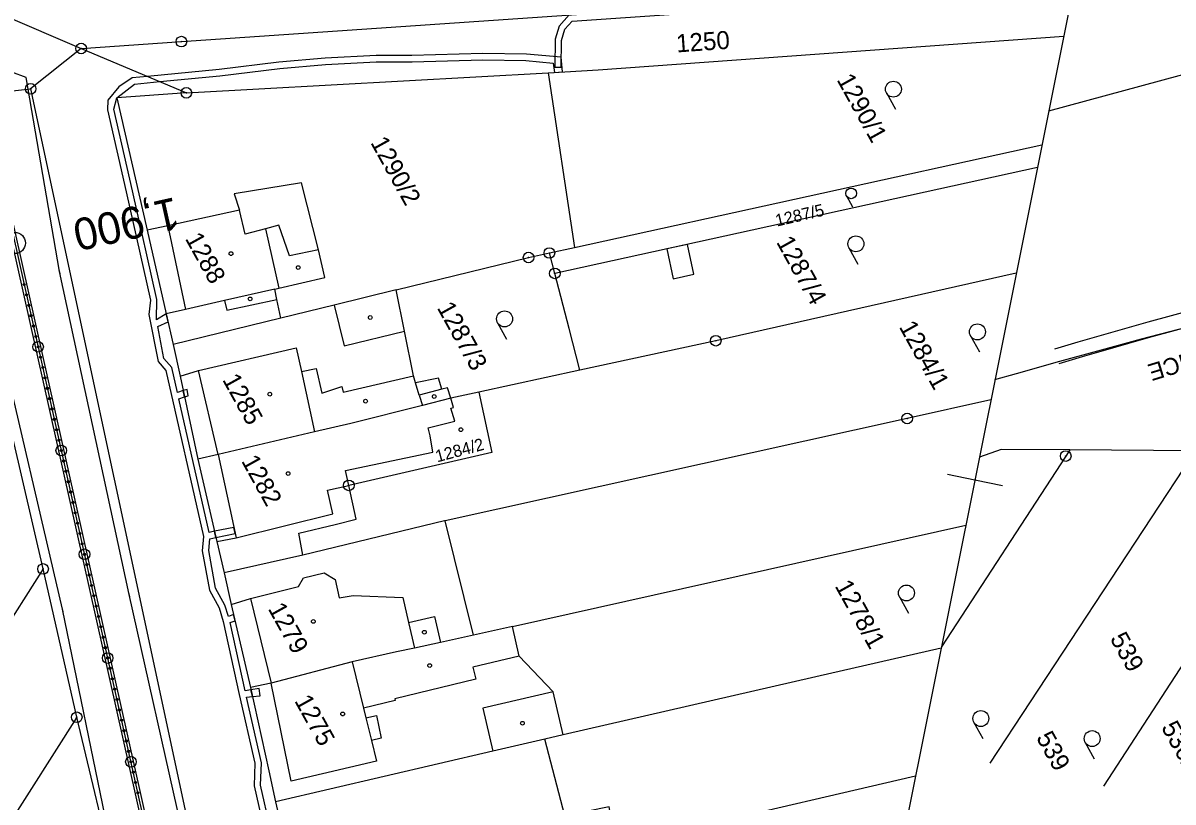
# Model space of a CAD drawing. Extents: x -548552 to -543113, y -1131925 to -1123599.
# Drawn here: x -548017.8 to -547909.6, y -1129833.4 to -1129760.1 of the extents above; entities that cross this region are included whole.
import ezdxf

# ---------------------------------------------------------------- set-up
doc = ezdxf.new("R2010")
doc.units = 0
for name, color, linetype in [('Hranice parcel', 7, 'Continuous'), ('NADZEMNÍ VEDENÍ VN', 7, 'Continuous'), ('Parcelní čísla', 7, 'Continuous'), ('Poz předměty', 7, 'Continuous'), ('Profile', 7, 'Continuous'), ('STANIČENÍ', 7, 'Continuous'), ('Vnitřní kresba', 7, 'Continuous'), ('Věcná břemena k části', 7, 'Continuous'), ('Značky bodu BP', 7, 'Continuous'), ('Značky budov', 7, 'Continuous'), ('Značky kultur', 7, 'Continuous'), ('ŽELEZNICE', 7, 'Continuous')]:
    doc.layers.add(name, color=color, linetype=linetype)

msp = doc.modelspace()

# ---------------------------------------------------------------- linework, layer by layer
at = {"layer": 'Hranice parcel'}
for p, q in [((-547921.25, -1129768.38), (-547893.05, -1129760.73)), ((-547921.25, -1129768.38), (-547893.05, -1129760.73)), ((-548012.34, -1129762.51), (-548017.09, -1129766.31)), ((-548012.34, -1129762.51), (-548002.43, -1129766.69)), ((-548002.43, -1129766.69), (-547968.36, -1129764.79)), ((-547968.36, -1129764.79), (-547965.9, -1129781.23)), ((-548026.4, -1129767.33), (-548017.09, -1129766.31)), ((-548026.4, -1129767.33), (-548017.09, -1129766.31)), ((-547965.9, -1129781.23), (-547921.89, -1129771.58)), ((-547922.32, -1129773.72), (-547967.75, -1129783.67)), ((-547968.26, -1129781.75), (-547965.9, -1129781.23)), ((-547967.75, -1129783.67), (-547968.26, -1129781.75)), ((-547993.53, -1129787.89), (-548003.66, -1129790.37)), ((-547965.41, -1129792.78), (-547974.91, -1129794.84)), ((-547974.91, -1129794.84), (-547977.55, -1129795.41)), ((-548015.92, -1129811.47), (-548018.75, -1129799.26)), ((-547907.46, -1129800.35), (-547919.28, -1129800.26)), ((-547975.4, -1129817.69), (-547978.07, -1129806.94)), ((-547991.48, -1129810.18), (-547998.89, -1129811.84)), ((-548015.92, -1129811.47), (-548041.34, -1129851.35)), ((-548012.75, -1129825.42), (-548015.92, -1129811.47)), ((-547971.74, -1129816.87), (-547975.4, -1129817.69)), ((-548012.75, -1129825.42), (-548032.91, -1129857.07)), ((-547966.95, -1129827.08), (-547968.68, -1129827.48)), ((-547961.98, -1129837.46), (-547933.79, -1129830.92)), ((-547994.03, -1129833.37), (-547991.57, -1129844.06))]:
    msp.add_line(p, q, dxfattribs=at)
for points in [[(-548019.13, -1129730.43), (-548027.65, -1129755.94), (-548012.34, -1129762.51)], [(-548012.34, -1129762.51), (-548002.9, -1129761.87), (-547963.89, -1129759.18), (-547918.79, -1129756.09)], [(-547968.36, -1129764.79), (-547963.68, -1129764.53), (-547919.84, -1129761.35)], [(-548017.09, -1129766.31), (-548001.35, -1129839.73), (-547987.65, -1129898.29)], [(-548017.09, -1129766.31), (-548001.35, -1129839.73), (-547987.65, -1129898.29)], [(-548002.43, -1129766.69), (-548008.99, -1129767.14), (-548006.13, -1129779.6)], [(-547993.53, -1129787.89), (-547993.91, -1129786.11), (-547994.12, -1129785.14), (-547993.73, -1129785.05), (-547989.39, -1129784.06), (-547989.99, -1129781.45), (-547991.58, -1129775.14), (-547997.92, -1129776.19), (-547997.44, -1129777.72), (-548004.19, -1129779.18), (-548006.13, -1129779.6)], [(-548006.13, -1129779.6), (-548004.32, -1129787.46), (-548003.66, -1129790.37)], [(-547982.68, -1129785.22), (-547970.22, -1129782.17), (-547968.26, -1129781.75)], [(-547965.41, -1129792.78), (-547966.39, -1129788.84), (-547967.75, -1129783.67)], [(-547924.31, -1129783.65), (-547952.6, -1129790), (-547965.41, -1129792.78)], [(-547982.68, -1129785.22), (-547988.51, -1129786.65), (-547993.53, -1129787.89)], [(-547977.55, -1129795.41), (-547977.85, -1129794.44), (-547978.37, -1129794.57), (-547978.7, -1129793.52), (-547980.86, -1129793.97), (-547981.05, -1129793.3), (-547981.9, -1129789.1), (-547982.68, -1129785.22)], [(-548003.66, -1129790.37), (-548003.02, -1129793.34), (-548001.35, -1129801.14)], [(-547977.55, -1129795.41), (-547980.21, -1129796.08), (-547986.94, -1129797.78), (-547990.36, -1129798.58), (-547999.43, -1129800.72), (-548001.35, -1129801.14)], [(-547987.14, -1129803.61), (-547987.45, -1129802.2), (-547979.23, -1129800.5), (-547979.49, -1129798.94), (-547979.66, -1129798.2), (-547977.16, -1129797.57), (-547977.54, -1129796.36), (-547977.28, -1129796.29), (-547977.55, -1129795.41)], [(-547974.91, -1129794.84), (-547973.68, -1129800.51), (-547987.14, -1129803.61)], [(-547926.7, -1129795.55), (-547934.58, -1129797.32), (-547978.07, -1129806.94)], [(-547919.28, -1129800.26), (-547919.66, -1129800.85), (-547931.36, -1129818.8)], [(-547919.28, -1129800.26), (-547925.73, -1129800.22), (-547927.78, -1129800.97)], [(-547907.46, -1129800.35), (-547907.81, -1129800.89), (-547926.79, -1129829.75)], [(-547895.43, -1129800.43), (-547896.76, -1129802.2), (-547916.11, -1129831.89)], [(-548001.35, -1129801.14), (-547999.57, -1129808.88), (-547998.89, -1129811.84)], [(-547991.48, -1129810.18), (-547991.84, -1129808.11), (-547988.43, -1129807.28), (-547986.45, -1129806.8), (-547987.14, -1129803.61)], [(-547978.07, -1129806.94), (-547978.14, -1129806.95), (-547991.48, -1129810.18)], [(-547971.74, -1129816.87), (-547929.06, -1129807.34)], [(-547998.89, -1129811.84), (-547998.2, -1129814.8), (-547996.41, -1129822.61)], [(-547966.95, -1129827.08), (-547967.89, -1129823.04), (-547971.12, -1129819.66), (-547971.74, -1129816.87)], [(-547975.4, -1129817.69), (-547978.5, -1129818.39), (-547980.95, -1129818.91), (-547982.66, -1129819.27), (-547986.82, -1129820.22), (-547994.45, -1129822.21), (-547996.41, -1129822.61)], [(-547931.38, -1129818.93), (-547943.18, -1129821.63), (-547966.95, -1129827.08)], [(-547996.41, -1129822.61), (-547994.68, -1129830.46), (-547994.03, -1129833.37)], [(-548007.22, -1129848.96), (-548009.02, -1129841.02), (-548012.75, -1129825.42)], [(-547968.68, -1129827.48), (-547973.58, -1129828.62), (-547994.03, -1129833.37)], [(-547961.98, -1129837.46), (-547962.63, -1129833.86), (-547966.81, -1129834.7), (-547968.68, -1129827.48)]]:
    msp.add_lwpolyline(points, dxfattribs=at)
at = {"layer": 'NADZEMNÍ VEDENÍ VN'}
msp.add_line((-548017.5, -1129765.24), (-548021.58, -1129763.72), dxfattribs=at)
at = {"layer": 'Poz předměty'}
for p, q in [((-548014.36, -1129783.5), (-548017.5, -1129765.24)), ((-548007.82, -1129813.86), (-548014.36, -1129783.5)), ((-548014.08, -1129815.26), (-548021.15, -1129785.02)), ((-548000.51, -1129846.47), (-548007.82, -1129813.86)), ((-548007.33, -1129848), (-548014.08, -1129815.26))]:
    msp.add_line(p, q, dxfattribs=at)
for points in [[(-548001.55, -1129858.01), (-548022.12, -1129766.11)], [(-548001.06, -1129857.9), (-548021.64, -1129766)], [(-547926.32, -1129793.66), (-547924.28, -1129793.07), (-547920.2, -1129791.93), (-547916.28, -1129790.85), (-547912.52, -1129789.84), (-547909.01, -1129788.91), (-547905.75, -1129788.07), (-547902.73, -1129787.3), (-547900.04, -1129786.63), (-547897.66, -1129786.05), (-547895.56, -1129785.55), (-547893.75, -1129785.13), (-547892.19, -1129784.78), (-547890.83, -1129784.49), (-547889.67, -1129784.25), (-547888.68, -1129784.06), (-547887.81, -1129783.91), (-547887.06, -1129783.79), (-547886.39, -1129783.69), (-547885.77, -1129783.61), (-547885.18, -1129783.53)]]:
    msp.add_lwpolyline(points, dxfattribs=at)
at = {"layer": 'Profile'}
for p, q in [((-547902.63, -1129675.5), (-547925.74, -1129790.79)), ((-547902.63, -1129675.5), (-547925.74, -1129790.79)), ((-547902.63, -1129675.5), (-547925.74, -1129790.79)), ((-547925.74, -1129790.79), (-547948.85, -1129906.07)), ((-547925.74, -1129790.79), (-547948.85, -1129906.07)), ((-547925.74, -1129790.79), (-547948.85, -1129906.07)), ((-547925.74, -1129790.79), (-547948.85, -1129906.07)), ((-547928.21, -1129803.12), (-547930.8, -1129802.6)), ((-547925.62, -1129803.64), (-547928.21, -1129803.12))]:
    msp.add_line(p, q, dxfattribs=at)
at = {"layer": 'STANIČENÍ'}
for points in [[(-548001.31, -1129857.96), (-548021.92, -1129765.88), (-548022.36, -1129763.91)], [(-548014.31, -1129783.72), (-548014.4, -1129783.31)], [(-548007.77, -1129814.08), (-548007.84, -1129813.74)], [(-548014.03, -1129815.48), (-548014.12, -1129815.09)]]:
    msp.add_lwpolyline(points, dxfattribs=at)
for centre, radius in [((-548018.58, -1129780.81), 1), ((-548017.7, -1129784.72), 0.1), ((-548017.48, -1129785.69), 0.1), ((-548017.26, -1129786.67), 0.1), ((-548017.05, -1129787.64), 0.1), ((-548016.83, -1129788.62), 0.1), ((-548016.39, -1129790.57), 0.5), ((-548016.61, -1129789.6), 0.1), ((-548016.39, -1129790.57), 0.1), ((-548016.17, -1129791.55), 0.1), ((-548015.95, -1129792.52), 0.1), ((-548015.74, -1129793.5), 0.1), ((-548015.52, -1129794.48), 0.1), ((-548015.3, -1129795.45), 0.1), ((-548015.08, -1129796.43), 0.1), ((-548014.86, -1129797.4), 0.1), ((-548014.64, -1129798.38), 0.1), ((-548014.43, -1129799.36), 0.1), ((-548014.21, -1129800.33), 0.5), ((-548014.21, -1129800.33), 0.1), ((-548013.99, -1129801.31), 0.1), ((-548013.77, -1129802.28), 0.1), ((-548013.55, -1129803.26), 0.1), ((-548013.33, -1129804.23), 0.1), ((-548013.11, -1129805.21), 0.1), ((-548012.9, -1129806.19), 0.1), ((-548012.68, -1129807.16), 0.1), ((-548012.46, -1129808.14), 0.1), ((-548012.24, -1129809.11), 0.1), ((-548012.02, -1129810.09), 0.5), ((-548012.02, -1129810.09), 0.1), ((-548011.8, -1129811.07), 0.1), ((-548011.59, -1129812.04), 0.1), ((-548011.37, -1129813.02), 0.1), ((-548011.15, -1129813.99), 0.1), ((-548010.93, -1129814.97), 0.1), ((-548010.71, -1129815.94), 0.1), ((-548010.49, -1129816.92), 0.1), ((-548010.27, -1129817.9), 0.1), ((-548010.06, -1129818.87), 0.1), ((-548009.84, -1129819.85), 0.5), ((-548009.84, -1129819.85), 0.1), ((-548009.62, -1129820.82), 0.1), ((-548009.4, -1129821.8), 0.1), ((-548009.18, -1129822.78), 0.1), ((-548008.96, -1129823.75), 0.1), ((-548008.75, -1129824.73), 0.1), ((-548008.53, -1129825.7), 0.1), ((-548008.31, -1129826.68), 0.1), ((-548008.09, -1129827.65), 0.1), ((-548007.87, -1129828.63), 0.1), ((-548007.65, -1129829.61), 0.5), ((-548007.65, -1129829.61), 0.1), ((-548007.43, -1129830.58), 0.1), ((-548007.22, -1129831.56), 0.1), ((-548007, -1129832.53), 0.1)]:
    msp.add_circle(centre, radius, dxfattribs=at)
at = {"layer": 'Vnitřní kresba'}
for p, q in [((-547996.91, -1129779.99), (-547997.44, -1129777.72)), ((-548004.19, -1129779.18), (-548002.52, -1129787.05)), ((-547993.72, -1129779.14), (-547994.98, -1129779.48)), ((-547992.71, -1129782.03), (-547993.72, -1129779.14)), ((-547994.98, -1129779.48), (-547996.91, -1129779.99)), ((-547994.98, -1129779.48), (-547993.73, -1129785.05)), ((-547989.99, -1129781.45), (-547992.71, -1129782.03)), ((-547994.12, -1129785.14), (-547998.85, -1129786.21)), ((-547998.85, -1129786.21), (-548002.52, -1129787.05)), ((-547998.85, -1129786.21), (-547998.62, -1129787.13)), ((-547998.62, -1129787.13), (-547993.91, -1129786.11)), ((-547988.51, -1129786.65), (-547987.57, -1129790.49)), ((-548002.52, -1129787.05), (-548004.32, -1129787.46)), ((-547987.57, -1129790.49), (-547981.9, -1129789.1)), ((-548001.29, -1129792.79), (-547992.09, -1129790.66)), ((-547992.09, -1129790.66), (-547991.6, -1129792.9)), ((-548003.02, -1129793.34), (-548001.29, -1129792.79)), ((-547999.43, -1129800.72), (-548001.29, -1129792.79)), ((-547991.6, -1129792.9), (-547990.21, -1129792.6)), ((-547991.6, -1129792.9), (-547990.36, -1129798.58)), ((-547990.21, -1129792.6), (-547989.69, -1129794.94)), ((-547987.67, -1129794.84), (-547981.05, -1129793.3)), ((-547989.69, -1129794.94), (-547987.8, -1129794.32)), ((-547987.8, -1129794.32), (-547987.67, -1129794.84)), ((-547980.52, -1129795.11), (-547980.86, -1129793.97)), ((-547978.37, -1129794.57), (-547980.52, -1129795.11)), ((-547980.52, -1129795.11), (-547980.21, -1129796.08)), ((-547999.43, -1129800.72), (-547997.76, -1129808.53)), ((-547989.15, -1129804.06), (-547988.13, -1129803.84)), ((-547988.65, -1129806.3), (-547989.15, -1129804.06)), ((-547988.13, -1129803.84), (-547987.14, -1129803.61)), ((-547997.76, -1129808.53), (-547988.65, -1129806.3)), ((-547999.57, -1129808.88), (-547997.76, -1129808.53)), ((-547991.89, -1129813.13), (-547991.41, -1129812.29)), ((-547991.41, -1129812.29), (-547989.45, -1129811.82)), ((-547989.45, -1129811.82), (-547988.44, -1129812.46)), ((-547988.44, -1129812.46), (-547988.04, -1129814.19)), ((-547996.4, -1129814.26), (-547991.89, -1129813.13)), ((-547998.2, -1129814.8), (-547996.4, -1129814.26)), ((-547996.4, -1129814.26), (-547994.45, -1129822.21)), ((-547988.04, -1129814.19), (-547986.73, -1129813.98)), ((-547986.73, -1129813.98), (-547982.06, -1129814.17)), ((-547982.06, -1129814.17), (-547981.51, -1129816.52)), ((-547981.51, -1129816.52), (-547979.08, -1129815.94)), ((-547979.08, -1129815.94), (-547978.5, -1129818.39)), ((-547981.51, -1129816.52), (-547980.95, -1129818.91)), ((-547986.82, -1129820.22), (-547985.76, -1129824.56)), ((-547971.12, -1129819.66), (-547975.46, -1129820.71)), ((-547975.46, -1129820.71), (-547975.19, -1129821.84)), ((-547992.57, -1129831.44), (-547994.45, -1129822.21)), ((-547975.19, -1129821.84), (-547982.8, -1129823.69)), ((-547967.89, -1129823.04), (-547974.52, -1129824.58)), ((-547982.77, -1129823.83), (-547985.76, -1129824.56)), ((-547985.76, -1129824.56), (-547985.53, -1129825.48)), ((-547982.8, -1129823.69), (-547982.77, -1129823.83)), ((-547974.52, -1129824.58), (-547973.58, -1129828.62)), ((-547985.53, -1129825.48), (-547984.55, -1129825.24)), ((-547985.53, -1129825.48), (-547985.01, -1129827.62)), ((-547984.55, -1129825.24), (-547984.1, -1129827.39)), ((-547984.1, -1129827.39), (-547985.01, -1129827.62)), ((-547985.01, -1129827.62), (-547984.55, -1129829.54)), ((-547984.55, -1129829.54), (-547989.62, -1129830.73)), ((-547989.62, -1129830.73), (-547992.57, -1129831.44))]:
    msp.add_line(p, q, dxfattribs=at)
at = {"layer": 'Věcná břemena k části'}
for points in [[(-547918.79, -1129756.09), (-547963.89, -1129759.18), (-547966.39, -1129759.35), (-547967.34, -1129760.4), (-547967.73, -1129761.65), (-547967.75, -1129764.26), (-547967.15, -1129764.27), (-547967.13, -1129761.75), (-547966.81, -1129760.7), (-547966.11, -1129759.93), (-547941.02, -1129758.22), (-547918.92, -1129756.74)], [(-548004.94, -1129765.63), (-547999.28, -1129765.1), (-547993.65, -1129764.39), (-547989.34, -1129764.01), (-547984.56, -1129763.77), (-547981.19, -1129763.78), (-547974.53, -1129763.59), (-547970.47, -1129763.65), (-547967.9, -1129763.88), (-547967.77, -1129764.76), (-547967.03, -1129764.72), (-547967.15, -1129763.34), (-547970.43, -1129763.05), (-547974.54, -1129763), (-547981.21, -1129763.18), (-547984.58, -1129763.16), (-547989.38, -1129763.41), (-547993.72, -1129763.8), (-547999.35, -1129764.5), (-548006.1, -1129765.14), (-548007.54, -1129765.27), (-548008.79, -1129766.11), (-548009.84, -1129767.36), (-548009.85, -1129768.28), (-548008.1, -1129776.01), (-548005.81, -1129786.18), (-548005.96, -1129787.52), (-548005.1, -1129791.96), (-548004.36, -1129792.8), (-548000.81, -1129808.41), (-548000.93, -1129809.76), (-548000.26, -1129813.46), (-547999.36, -1129815.13), (-547998.96, -1129816.42), (-547997.45, -1129823.27), (-547995.98, -1129829.75), (-547996.05, -1129831.86), (-547995.11, -1129836.03)], [(-548004.94, -1129765.63), (-547999.28, -1129765.1), (-547993.65, -1129764.39), (-547989.34, -1129764.01), (-547984.56, -1129763.77), (-547981.19, -1129763.78), (-547974.53, -1129763.59), (-547970.47, -1129763.65), (-547967.9, -1129763.88), (-547967.77, -1129764.76), (-547967.03, -1129764.72), (-547967.15, -1129763.34), (-547970.43, -1129763.05), (-547974.54, -1129763), (-547981.21, -1129763.18), (-547984.58, -1129763.16), (-547989.38, -1129763.41), (-547993.72, -1129763.8), (-547999.35, -1129764.5), (-548006.1, -1129765.14), (-548007.54, -1129765.27), (-548008.79, -1129766.11), (-548009.84, -1129767.36), (-548009.85, -1129768.28), (-548008.1, -1129776.01), (-548005.81, -1129786.18), (-548005.96, -1129787.52), (-548005.1, -1129791.96), (-548004.36, -1129792.8), (-548000.81, -1129808.41), (-548000.93, -1129809.76), (-548000.26, -1129813.46), (-547999.36, -1129815.13), (-547998.96, -1129816.42), (-547997.45, -1129823.27), (-547995.98, -1129829.75), (-547996.05, -1129831.86), (-547995.11, -1129836.03)], [(-547994.54, -1129835.83), (-547995.45, -1129831.8), (-547995.37, -1129829.7), (-547996.76, -1129823.53), (-547996.21, -1129823.47), (-547996.36, -1129822.84), (-547996.9, -1129822.94), (-547998.32, -1129816.52), (-547997.85, -1129816.34), (-547997.99, -1129815.74), (-547998.48, -1129815.95), (-547998.8, -1129814.89), (-547999.68, -1129813.27), (-548000.33, -1129809.73), (-548000.23, -1129808.64), (-547999.66, -1129808.51), (-547999.79, -1129807.93), (-548000.29, -1129808.04), (-548003.14, -1129795.46), (-548002.6, -1129795.29), (-548002.73, -1129794.7), (-548003.27, -1129794.88), (-548003.81, -1129792.52), (-548004.54, -1129791.69), (-548005.12, -1129788.65), (-548004.15, -1129788.23), (-548004.32, -1129787.46), (-548005.24, -1129788.04), (-548005.2, -1129786.14), (-548007.51, -1129775.89), (-548009.25, -1129768.21), (-548008.99, -1129767.14), (-548007.33, -1129765.86), (-548004.94, -1129765.63)], [(-547994.54, -1129835.83), (-547995.45, -1129831.8), (-547995.37, -1129829.7), (-547996.76, -1129823.53), (-547996.21, -1129823.47), (-547996.36, -1129822.84), (-547996.9, -1129822.94), (-547998.32, -1129816.52), (-547997.85, -1129816.34), (-547997.99, -1129815.74), (-547998.48, -1129815.95), (-547998.8, -1129814.89), (-547999.68, -1129813.27), (-548000.33, -1129809.73), (-548000.23, -1129808.64), (-547999.66, -1129808.51), (-547999.79, -1129807.93), (-548000.29, -1129808.04), (-548003.14, -1129795.46), (-548002.6, -1129795.29), (-548002.73, -1129794.7), (-548003.27, -1129794.88), (-548003.81, -1129792.52), (-548004.54, -1129791.69), (-548005.12, -1129788.65), (-548004.15, -1129788.23), (-548004.32, -1129787.46), (-548005.24, -1129788.04), (-548005.2, -1129786.14), (-548007.51, -1129775.89), (-548009.25, -1129768.21), (-548008.99, -1129767.14), (-548007.33, -1129765.86), (-548004.94, -1129765.63)]]:
    msp.add_lwpolyline(points, dxfattribs=at)
for points in [[(-547954.65, -1129783.74), (-547955.26, -1129780.94), (-547957.21, -1129781.36), (-547956.6, -1129784.17)], [(-548002.73, -1129794.7), (-548002.6, -1129795.29), (-548002.25, -1129795.18), (-548002.36, -1129794.59)], [(-547999.79, -1129807.93), (-547999.66, -1129808.51), (-547997.85, -1129808.14), (-547997.97, -1129807.56)], [(-547996.21, -1129823.47), (-547995.49, -1129823.41), (-547995.58, -1129822.71), (-547996.36, -1129822.84)]]:
    msp.add_lwpolyline(points, close=True, dxfattribs=at)
at = {"layer": 'Značky bodu BP'}
for centre, radius in [((-548002.9, -1129761.87), 0.5), ((-548002.9, -1129761.87), 0.0303), ((-548012.34, -1129762.51), 0.5), ((-548012.34, -1129762.51), 0.0303), ((-548017.09, -1129766.31), 0.5), ((-548017.09, -1129766.31), 0.5), ((-548002.43, -1129766.69), 0.5), ((-548017.09, -1129766.31), 0.0303), ((-548017.09, -1129766.31), 0.0303), ((-548002.43, -1129766.69), 0.0303), ((-547968.26, -1129781.75), 0.5), ((-547970.22, -1129782.17), 0.5), ((-547970.22, -1129782.17), 0.0303), ((-547968.26, -1129781.75), 0.0303), ((-547967.75, -1129783.67), 0.5), ((-547967.75, -1129783.67), 0.0303), ((-547952.6, -1129790), 0.5), ((-547952.6, -1129790), 0.0303), ((-547934.58, -1129797.32), 0.5), ((-547934.58, -1129797.32), 0.0303), ((-547919.66, -1129800.85), 0.5), ((-547919.66, -1129800.85), 0.0303), ((-547987.14, -1129803.61), 0.5), ((-547987.14, -1129803.61), 0.0303), ((-548015.92, -1129811.47), 0.5), ((-548015.92, -1129811.47), 0.0303), ((-548012.75, -1129825.42), 0.5), ((-548012.75, -1129825.42), 0.0303)]:
    msp.add_circle(centre, radius, dxfattribs=at)
at = {"layer": 'Značky budov'}
for centre in [(-547998.23, -1129781.81), (-547991.9, -1129783.12), (-547996.43, -1129786.07), (-547985.12, -1129787.82), (-547994.58, -1129795.03), (-547979.1, -1129795.25), (-547985.56, -1129795.69), (-547976.59, -1129798.37), (-547992.86, -1129802.5), (-547990.48, -1129816.41), (-547980.03, -1129817.42), (-547979.53, -1129820.56), (-547987.72, -1129825.11), (-547970.8, -1129825.98)]:
    msp.add_circle(centre, 0.175, dxfattribs=at)
at = {"layer": 'Značky kultur'}
for p, q in [((-547936.54, -1129766.7), (-547935.69, -1129768.23)), ((-547940.29, -1129776.38), (-547939.72, -1129777.4)), ((-547940.07, -1129781.26), (-547939.22, -1129782.79)), ((-547973.14, -1129788.32), (-547972.29, -1129789.85)), ((-547928.62, -1129789.53), (-547927.77, -1129791.06)), ((-547935.31, -1129814.09), (-547934.46, -1129815.62)), ((-547928.31, -1129825.9), (-547927.46, -1129827.43)), ((-547917.82, -1129827.79), (-547916.97, -1129829.32))]:
    msp.add_line(p, q, dxfattribs=at)
for centre, radius in [((-547935.88, -1129766.34), 0.75), ((-547939.85, -1129776.14), 0.502), ((-547939.41, -1129780.89), 0.75), ((-547972.48, -1129787.95), 0.75), ((-547927.97, -1129789.17), 0.75), ((-547934.65, -1129813.73), 0.75), ((-547927.65, -1129825.54), 0.75), ((-547917.17, -1129827.43), 0.75)]:
    msp.add_circle(centre, radius, dxfattribs=at)
at = {"layer": 'ŽELEZNICE'}
for centre, radius in [((-547900.33, -1130323.22), 585.63), ((-547900.33, -1130323.22), 584.19), ((-547754.73, -1130352.4), 585.63), ((-547754.73, -1130352.4), 584.19)]:
    msp.add_arc(centre, radius, 92.19883, 106.46382, dxfattribs=at)

# ---------------------------------------------------------------- texts
at = {"layer": 'Parcelní čísla'}
for s, height, rotation, p in [('1250', 1.7, 4.0429, (-547956.27, -1129762.89)), ('1290/1', 1.7, 299.0429, (-547941.25, -1129765.45)), ('1290/2', 1.7, 299.0429, (-547985.14, -1129771.36)), ('1287/5', 1.139, 13.0429, (-547946.85, -1129779.27)), ('1288', 1.7, 299.0429, (-548002.59, -1129780.39)), ('1287/4', 1.7, 299.0429, (-547946.94, -1129780.72)), ('1287/3', 1.7, 299.0429, (-547978.88, -1129786.9)), ('1284/1', 1.7, 299.0429, (-547935.39, -1129788.69)), ('1285', 1.7, 299.0429, (-547999.08, -1129793.67)), ('1284/2', 1.139, 15.0429, (-547978.82, -1129801.45)), ('1282', 1.7, 299.0429, (-547997.3, -1129801.31)), ('1278/1', 1.7, 299.0429, (-547941.43, -1129813.07)), ('1279', 1.7, 299.0429, (-547994.79, -1129815.2)), ('539', 1.7, 299.0429, (-547915.53, -1129818.01)), ('1275', 1.7, 299.0429, (-547992.3, -1129823.87)), ('536/1', 1.7, 299.0429, (-547910.71, -1129826.36)), ('539', 1.7, 299.0429, (-547922.48, -1129827.33))]:
    msp.add_text(s, height=height, rotation=rotation, dxfattribs=at).set_placement(p)
at = {"layer": 'STANIČENÍ'}
msp.add_text('1,900', height=3, rotation=192.6173, dxfattribs=at).set_placement((-548003.51, -1129776.48))
at = {"layer": 'ŽELEZNICE'}
msp.add_text('NEZAMYSLICE', height=1.6, rotation=197.1245, dxfattribs=at).set_placement((-547897.62, -1129787.84))

doc.saveas('drawing.dxf')
